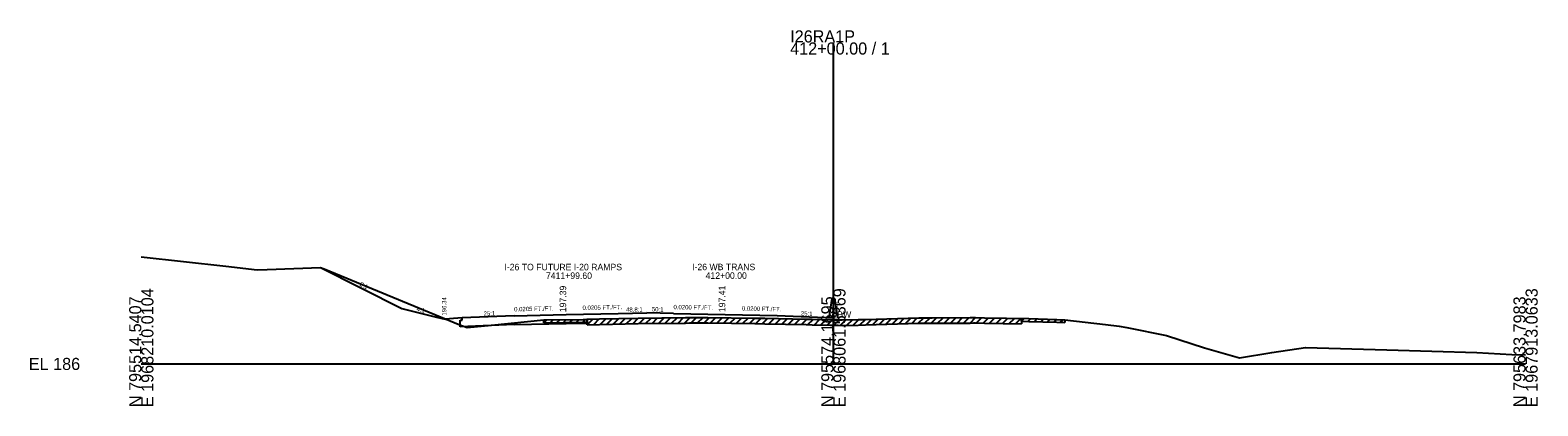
# Model space of a CAD drawing. Extents: x -44 to 4323, y -10 to 9601.
# Drawn here: x -25.7 to 322.8, y 7490.3 to 7577.1 of the extents above; entities that cross this region are included whole.
import ezdxf

# ---------------------------------------------------------------- set-up
doc = ezdxf.new("R2010")
doc.units = 0
for name, color, linetype in [('1', 7, 'Continuous'), ('DateStamp', 7, 'Continuous'), ('NotForConst', 7, 'Continuous'), ('QCQA', 7, 'Continuous'), ('RD_SHT_Bndy', 7, 'Continuous'), ('RD_SHT_Iplotshp', 7, 'Continuous'), ('RD_SHT_TX', 7, 'Continuous'), ('RD_TX_Misc1', 7, 'Continuous'), ('RD_XS_ExGround', 7, 'Continuous'), ('RD_XS_Misc_Line', 7, 'Continuous'), ('RD_XS_Pave', 7, 'Continuous'), ('RD_XS_PaveShd', 7, 'Continuous'), ('RD_XS_TX_Elev_PR', 7, 'Continuous'), ('RD_XS_TX_Profile', 7, 'Continuous'), ('RD_XS_TX_ShdSlope', 7, 'Continuous'), ('RD_XS_TX_Slope', 7, 'Continuous'), ('seal', 7, 'Continuous'), ('TR SN EXTRUDED PANEL SIGNS - GROUND MOUNTED', 7, 'Continuous')]:
    doc.layers.add(name, color=color, linetype=linetype)

msp = doc.modelspace()

# ---------------------------------------------------------------- linework, layer by layer
at = {"layer": 'DateStamp'}
msp.add_lwpolyline([(0, 7524.77), (19.55, 7522.61), (26.82, 7521.77), (29.11, 7521.83), (41.43, 7522.25), (42.26, 7521.94), (46.17, 7520.35), (73.62, 7509.07), (75.36, 7508.39), (80.93, 7508.95), (93.09, 7510.15), (102.11, 7510.3), (102.99, 7510.32), (105.96, 7510.38), (114.83, 7510.56), (125.81, 7510.7), (126.73, 7510.72), (130.01, 7510.74), (130.45, 7510.74), (130.93, 7510.73), (141.8, 7510.6), (144.17, 7510.55), (153.69, 7510.36), (155.09, 7510.31), (159.31, 7510.2), (160, 7510.18), (161.12, 7510.17), (162.05, 7510.15), (165.71, 7510.24), (167.43, 7510.29), (179.76, 7510.63), (180.41, 7510.65), (182.81, 7510.66), (191.62, 7510.7), (192.4, 7510.71), (192.86, 7510.72), (194.94, 7510.68), (205.16, 7510.46), (211.68, 7510.27), (213.47, 7510.2), (222.87, 7509.12), (226.09, 7508.74), (227.81, 7508.44), (237.02, 7506.55), (245.79, 7503.71), (253.89, 7501.4), (261.38, 7502.63), (269.15, 7503.76), (287.95, 7503.26), (308.72, 7502.65), (316.84, 7502.21), (320, 7502.06)], dxfattribs=at)
at = {"layer": 'NotForConst'}
for p, q in [((93.09, 7509.53), (93.73, 7510.16)), ((94.59, 7509.55), (95.23, 7510.19)), ((96.09, 7509.58), (96.73, 7510.21)), ((97.59, 7509.6), (98.23, 7510.24)), ((99.09, 7509.63), (99.73, 7510.26)), ((100.59, 7509.65), (101.23, 7510.29)), ((102.09, 7509.68), (102.73, 7510.31)), ((103.09, 7509.07), (104.37, 7510.35)), ((104.59, 7509.1), (105.87, 7510.38)), ((106.09, 7509.14), (107.37, 7510.41)), ((107.59, 7509.17), (108.87, 7510.44)), ((109.09, 7509.2), (110.37, 7510.47)), ((110.59, 7509.23), (111.87, 7510.5)), ((112.09, 7509.26), (113.37, 7510.53)), ((113.59, 7509.29), (114.87, 7510.56)), ((115.09, 7509.32), (116.36, 7510.58)), ((116.59, 7509.34), (117.86, 7510.6)), ((118.09, 7509.36), (119.36, 7510.62)), ((119.59, 7509.37), (120.86, 7510.64)), ((121.09, 7509.39), (122.36, 7510.66)), ((122.59, 7509.41), (123.86, 7510.68)), ((124.09, 7509.43), (125.36, 7510.7)), ((125.59, 7509.45), (126.86, 7510.72)), ((127.09, 7509.47), (128.35, 7510.73)), ((128.59, 7509.48), (129.85, 7510.74)), ((130.09, 7509.49), (131.34, 7510.73)), ((131.59, 7509.47), (132.83, 7510.71)), ((133.09, 7509.46), (134.33, 7510.69)), ((134.59, 7509.44), (135.83, 7510.67)), ((136.09, 7509.42), (137.33, 7510.65)), ((137.59, 7509.4), (138.83, 7510.64)), ((139.09, 7509.38), (140.33, 7510.62)), ((140.59, 7509.36), (141.83, 7510.6)), ((142.09, 7509.34), (143.32, 7510.57)), ((143.59, 7509.31), (144.82, 7510.54)), ((145.09, 7509.28), (146.32, 7510.51)), ((146.59, 7509.25), (147.82, 7510.48)), ((148.09, 7509.22), (149.32, 7510.45)), ((149.59, 7509.19), (150.82, 7510.42)), ((151.09, 7509.16), (152.32, 7510.39)), ((152.59, 7509.13), (153.82, 7510.35)), ((154.09, 7509.09), (155.3, 7510.3)), ((155.59, 7509.04), (156.81, 7510.26)), ((157.09, 7509), (158.31, 7510.22)), ((158.59, 7508.96), (159.82, 7510.19)), ((160.09, 7508.93), (161.32, 7510.16)), ((161.59, 7508.91), (162.86, 7510.17)), ((163.09, 7508.93), (164.38, 7510.21)), ((164.59, 7508.97), (165.88, 7510.25)), ((166.09, 7509), (167.38, 7510.29)), ((167.59, 7509.04), (168.88, 7510.33)), ((169.09, 7509.08), (170.38, 7510.37)), ((170.59, 7509.13), (171.88, 7510.41)), ((172.09, 7509.17), (173.38, 7510.45)), ((173.59, 7509.21), (174.88, 7510.5)), ((175.09, 7509.25), (176.38, 7510.54)), ((176.59, 7509.29), (177.88, 7510.58)), ((178.09, 7509.34), (179.38, 7510.62)), ((179.59, 7509.38), (180.87, 7510.65)), ((181.09, 7509.4), (182.35, 7510.66)), ((182.59, 7509.41), (183.85, 7510.67)), ((184.09, 7509.42), (185.35, 7510.67)), ((185.59, 7509.42), (186.85, 7510.68)), ((187.09, 7509.43), (188.35, 7510.69)), ((188.59, 7509.44), (189.85, 7510.69)), ((190.09, 7509.44), (191.35, 7510.7)), ((191.59, 7509.45), (192.86, 7510.72)), ((193.09, 7509.46), (194.32, 7510.69)), ((194.59, 7509.43), (195.82, 7510.66)), ((196.09, 7509.4), (197.32, 7510.63)), ((197.59, 7509.37), (198.82, 7510.59)), ((199.09, 7509.34), (200.32, 7510.56)), ((200.59, 7509.31), (201.82, 7510.53)), ((202.09, 7509.28), (203.32, 7510.5)), ((203.47, 7509.87), (204.08, 7510.48)), ((204.97, 7509.84), (205.57, 7510.45)), ((206.47, 7509.8), (207.07, 7510.41)), ((207.97, 7509.75), (208.57, 7510.36)), ((209.47, 7509.71), (210.07, 7510.32)), ((210.97, 7509.66), (211.57, 7510.27)), ((212.47, 7509.61), (213.07, 7510.22))]:
    msp.add_line(p, q, dxfattribs=at)
at = {"layer": 'QCQA'}
for p, q in [((103.09, 7510.32), (105.96, 7510.38)), ((103.09, 7510.32), (103.09, 7509.45)), ((105.96, 7510.38), (114.83, 7510.56)), ((114.83, 7510.56), (125.81, 7510.7)), ((125.81, 7510.7), (126.73, 7510.72)), ((126.73, 7510.72), (130.01, 7510.74)), ((130.01, 7510.74), (130.45, 7510.74)), ((130.45, 7510.74), (130.93, 7510.73)), ((130.93, 7510.73), (141.8, 7510.6)), ((141.8, 7510.6), (144.17, 7510.55)), ((144.17, 7510.55), (153.69, 7510.36)), ((153.69, 7510.36), (155.09, 7510.31)), ((155.09, 7510.31), (159.31, 7510.2)), ((159.31, 7510.2), (160, 7510.18))]:
    msp.add_line(p, q, dxfattribs=at)
at = {"layer": 'RD_SHT_Bndy'}
for p, q in [((160, 7500), (160, 7574.3)), ((0, 7500), (160, 7500)), ((160, 7500), (320, 7500))]:
    msp.add_line(p, q, dxfattribs=at)
at = {"layer": 'RD_SHT_Iplotshp'}
for p, q in [((93.09, 7509.53), (93.09, 7510.15)), ((93.09, 7509.53), (102.11, 7509.68)), ((102.11, 7509.68), (102.99, 7509.69)), ((102.99, 7509.69), (103.09, 7509.7)), ((103.09, 7509.07), (103.09, 7510.32)), ((103.09, 7510.32), (103.09, 7509.7)), ((103.09, 7509.07), (105.96, 7509.13)), ((105.96, 7509.13), (114.83, 7509.31)), ((114.83, 7509.31), (125.81, 7509.45)), ((125.81, 7509.45), (126.73, 7509.47)), ((126.73, 7509.47), (130.01, 7509.49)), ((130.01, 7509.49), (130.45, 7509.49)), ((130.45, 7509.49), (130.93, 7509.48)), ((130.93, 7509.48), (141.8, 7509.35)), ((141.8, 7509.35), (144.17, 7509.3)), ((144.17, 7509.3), (153.69, 7509.11)), ((153.69, 7509.11), (155.09, 7509.06)), ((155.09, 7509.06), (159.31, 7508.95)), ((159.31, 7508.95), (160, 7508.93)), ((160, 7508.93), (161.12, 7508.92)), ((161.12, 7508.92), (162.05, 7508.9)), ((162.05, 7508.9), (165.71, 7508.99)), ((165.71, 7508.99), (167.43, 7509.04)), ((167.43, 7509.04), (179.76, 7509.38)), ((179.76, 7509.38), (180.41, 7509.4)), ((180.41, 7509.4), (182.81, 7509.41)), ((182.81, 7509.41), (191.62, 7509.45)), ((191.62, 7509.45), (192.4, 7509.46)), ((192.4, 7509.46), (192.86, 7509.47)), ((192.86, 7509.47), (194.94, 7509.43)), ((194.94, 7509.43), (203.47, 7509.25)), ((203.47, 7510.5), (203.47, 7509.25)), ((203.47, 7509.87), (203.47, 7510.5)), ((203.47, 7509.87), (205.16, 7509.84)), ((205.16, 7509.84), (211.68, 7509.64)), ((211.68, 7509.64), (213.47, 7509.58)), ((213.47, 7510.2), (213.47, 7509.58))]:
    msp.add_line(p, q, dxfattribs=at)
at = {"layer": 'RD_TX_Misc1'}
for p in [(68.21, 7510.84), (72.21, 7510.5)]:
    msp.add_line(p, (70.21, 7510.34), dxfattribs=at)
at = {"layer": 'RD_XS_Misc_Line'}
for p, q in [((73.71, 7510.08), (74.21, 7510.1)), ((73.71, 7508.6), (73.71, 7510.08)), ((86.22, 7509.1), (73.71, 7508.6)), ((74.21, 7510.1), (74.21, 7510.66)), ((86.22, 7509.1), (98.22, 7509.35)), ((98.22, 7509.35), (103.09, 7509.45))]:
    msp.add_line(p, q, dxfattribs=at)
at = {"layer": 'RD_XS_Pave'}
for p, q in [((41.41, 7522.25), (60.22, 7512.84)), ((60.22, 7512.84), (68.21, 7510.84))]:
    msp.add_line(p, q, dxfattribs=at)
at = {"layer": 'RD_XS_PaveShd'}
msp.add_line((74.21, 7510.66), (72.21, 7510.5), dxfattribs=at)
at = {"layer": 'RD_XS_TX_Elev_PR'}
for p, q in [((86.22, 7511.14), (74.21, 7510.66)), ((110.22, 7511.64), (116.85, 7511.77)), ((123, 7511.65), (116.85, 7511.77)), ((147, 7511.17), (160, 7510.65)), ((160, 7510.65), (160, 7510.18))]:
    msp.add_line(p, q, dxfattribs=at)
at = {"layer": 'RD_XS_TX_ShdSlope'}
for p, q in [((159, 7510.67), (159.67, 7515.15)), ((160, 7515.15), (159.67, 7515.15)), ((160, 7515.15), (160.33, 7515.15)), ((161, 7510.67), (160.33, 7515.15))]:
    msp.add_line(p, q, dxfattribs=at)
at = {"layer": 'RD_XS_TX_Slope'}
for p, q in [((86.22, 7511.14), (98.22, 7511.39)), ((98.22, 7511.39), (110.22, 7511.64)), ((123, 7511.65), (135, 7511.41)), ((135, 7511.41), (147, 7511.17))]:
    msp.add_line(p, q, dxfattribs=at)

# ---------------------------------------------------------------- texts
at = {"layer": '1'}
for s, p in [('I-26 TO FUTURE I-20 RAMPS', (83.94, 7521.64)), ('I-26 WB TRANS', (127.33, 7521.66)), ('7411+99.60', (93.54, 7519.64)), ('412+00.00', (130.45, 7519.66))]:
    msp.add_text(s, height=1.5, dxfattribs=at).set_placement(p)
at = {"layer": 'RD_SHT_Bndy'}
for s, p in [('I26RA1P', (150, 7574.3)), ('412+00.00 / 1', (150, 7571.5)), ('EL 186', (-26, 7498.6))]:
    msp.add_text(s, height=2.8, dxfattribs=at).set_placement(p)
for s, p in [('N 795514.5407', (0, 7490)), ('E 1968210.0104', (2.8, 7490)), ('N 795574.1695', (160, 7490)), ('E 1968061.5369', (162.8, 7490)), ('N 795633.7983', (320, 7490)), ('E 1967913.0633', (322.8, 7490))]:
    msp.add_text(s, height=2.8, rotation=90, dxfattribs=at).set_placement(p)
at = {"layer": 'RD_SHT_TX'}
msp.add_text('196.18', height=1, rotation=90, dxfattribs=at).set_placement((161, 7510.18))
at = {"layer": 'RD_XS_ExGround'}
for s, rotation, p in [('25:1', 2.29, (79.15, 7511.11)), ('48.8:1', 1.1732, (112.08, 7512.04)), ('50:1', 358.8542, (118.02, 7512.15)), ('25:1', 357.7094, (152.46, 7511.2))]:
    msp.add_text(s, height=1, rotation=rotation, dxfattribs=at).set_placement(p)
at = {"layer": 'RD_XS_TX_Profile'}
msp.add_text('WBW', height=1.5, dxfattribs=at).set_placement((159, 7510.67))
at = {"layer": 'seal'}
for s, p in [(' 197.39', (98.22, 7511.39)), (' 197.41', (135, 7511.41))]:
    msp.add_text(s, height=1.5, rotation=90, dxfattribs=at).set_placement(p)
at = {"layer": 'TR SN EXTRUDED PANEL SIGNS - GROUND MOUNTED'}
for s, rotation, p in [('2:1', 333.4349, (50.41, 7518.09)), ('196.34', 90, (70.52, 7511.18)), ('4:1', 345.9638, (63.56, 7512.27)), ('0.0205 FT./FT.', 1.1755, (86.2, 7512.14)), ('0.0205 FT./FT.', 1.1732, (102.01, 7512.47)), ('0.0200 FT./FT.', 358.8542, (123.02, 7512.65)), ('0.0200 FT./FT.', 358.8542, (138.83, 7512.33))]:
    msp.add_text(s, height=1, rotation=rotation, dxfattribs=at).set_placement(p)

doc.saveas('drawing.dxf')
